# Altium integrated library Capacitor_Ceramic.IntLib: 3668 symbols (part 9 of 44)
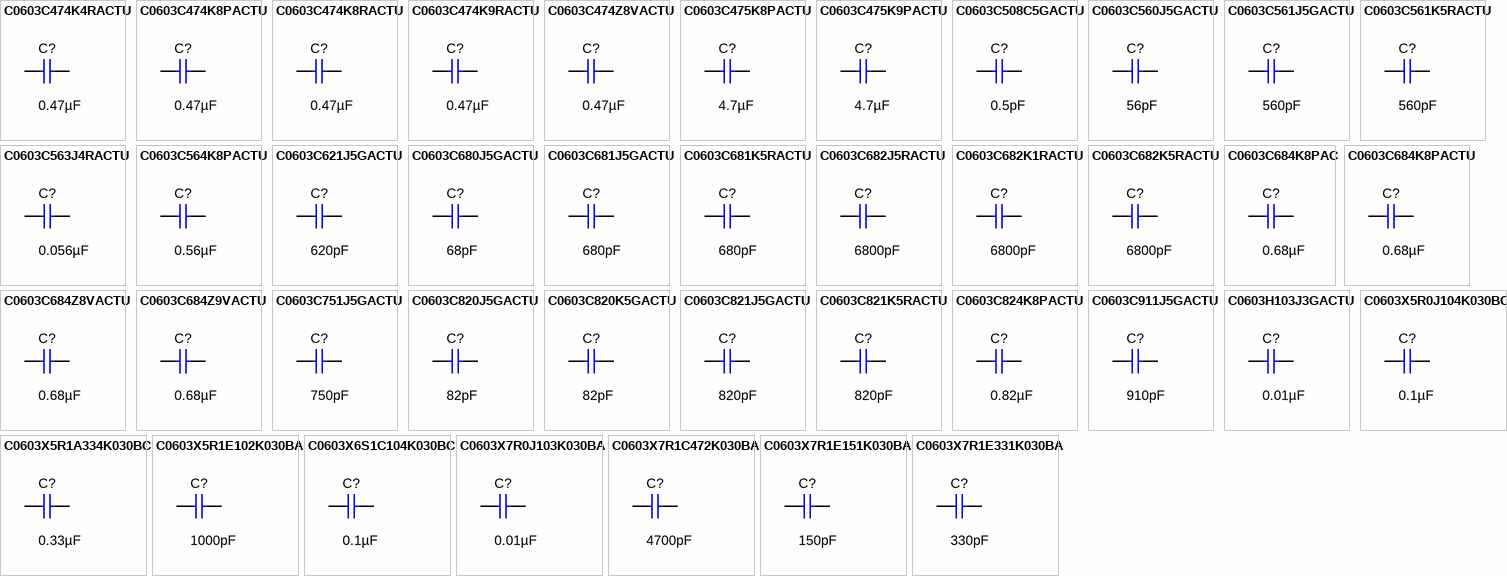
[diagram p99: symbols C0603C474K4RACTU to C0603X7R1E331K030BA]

## C0603C474Z8VACTU
designator C?  ValueDisplayed: 0.47µF  (hidden comment: C0603C474Z8VACTU)
CAP, CERM, 0.47 µF, 10 V,+80/-20%, Y5V, 0603; Manufacturer: Kemet; Polarized: N; CompType: Capacitor; Value: 0.47uF; U/M: EA; Cap_F: 0.00000047; Tolerance_%: 80; VDC_V: 10; Value2: 10V; TaMin_C: -30; TaMax_C: 85; Cap_Case: 0603; SizeArea_mm2: 1.28; SizeAreaWB_mm2: 4.68; SizeX_mm: 1.6; SizeY_mm: 0.8; SizeZ_mm: 1; AEC Category: Q200; Green_Lifecycle: Not Set; Green_REACh: Incomplete
signal-integrity model Cap
simulation model Cap
footprint 0603
footprint 0603M
footprint 0603L
footprint 0603_HV
footprint 0603S
pins: 1, 2

## C0603C475K8PACTU
designator C?  ValueDisplayed: 4.7µF  (hidden comment: C0603C475K8PACTU)
CAP, CERM, 4.7 µF, 10 V,+/- 10%, X5R, 0603; Manufacturer: Kemet; Polarized: N; CompType: Capacitor; Value: 4.7uF; U/M: EA; Cap_F: 0.0000047; Tolerance_%: 10; ESR_ohm: 0.006; Value1: 0.006 ohm; Value2: 10V; IRMS_A: 7.24; TaMin_C: -55; TaMax_C: 85; Cap_Case: 0603; SizeArea_mm2: 1.28; SizeAreaWB_mm2: 4.68; SizeX_mm: 1.6; SizeY_mm: 0.8; SizeZ_mm: 1; AEC Category: Q200; Green_Lifecycle: Active; Green_REACh: Passed
signal-integrity model Cap
simulation model Cap
footprint 0603
footprint 0603M
footprint 0603L
footprint 0603_HV
footprint 0603S
pins: 1, 2

## C0603C475K9PACTU
designator C?  ValueDisplayed: 4.7µF  (hidden comment: C0603C475K9PACTU)
CAP, CERM, 4.7 µF, 6.3 V,+/- 10%, X5R, 0603; Manufacturer: Kemet; Polarized: N; CompType: Capacitor; Value: 4.7uF; U/M: EA; Cap_F: 0.0000047; Tolerance_%: 10; ESR_ohm: 0.006; Value1: 0.006 ohm; VDC_V: 6.3; Value2: 6.3V; IRMS_A: 7.24; TaMin_C: -55; TaMax_C: 85; Cap_Case: 0603; SizeArea_mm2: 1.28; SizeAreaWB_mm2: 4.68; SizeX_mm: 1.6; SizeY_mm: 0.8; SizeZ_mm: 1; AEC Category: Q200; Green_Lifecycle: Active; Green_REACh: Passed
signal-integrity model Cap
simulation model Cap
footprint 0603
footprint 0603M
footprint 0603L
footprint 0603_HV
footprint 0603S
pins: 1, 2

## C0603C508C5GACTU
designator C?  ValueDisplayed: 0.5pF  (hidden comment: C0603C508C5GACTU)
CAP, CERM, 0.5 pF, 50 V,+/- 50%, C0G/NP0, 0603; Manufacturer: Kemet; Polarized: N; CompType: Capacitor; Value: 0.5pF; U/M: EA; Cap_F: 0.0000000000005; Tolerance_%: 50; Value2: 50V; TaMin_C: -55; TaMax_C: 125; Cap_Case: 0603; SizeArea_mm2: 1.28; SizeAreaWB_mm2: 4.68; SizeX_mm: 1.6; SizeY_mm: 0.8; SizeZ_mm: 1; AEC Category: Q200; Green_Lifecycle: Not Set; Green_REACh: Incomplete
signal-integrity model Cap
simulation model Cap
footprint 0603
footprint 0603M
footprint 0603L
footprint 0603_HV
footprint 0603S
pins: 1, 2

## C0603C560J5GACTU
designator C?  ValueDisplayed: 56pF  (hidden comment: C0603C560J5GACTU)
CAP, CERM, 56 pF, 50 V,+/- 5%, C0G/NP0, 0603; Manufacturer: Kemet; Polarized: N; CompType: Capacitor; Value: 56pF; U/M: EA; Cap_F: 0.000000000056; Tolerance_%: 5; VDC_V: 50; Value2: 50V; TaMin_C: -55; TaMax_C: 125; Cap_Case: 0603; SizeArea_mm2: 1.28; SizeAreaWB_mm2: 4.68; SizeX_mm: 1.6; SizeY_mm: 0.8; SizeZ_mm: 1; AEC Category: Q200; Green_Lifecycle: Active; Green_REACh: Passed
signal-integrity model Cap
simulation model Cap
footprint 0603
footprint 0603M
footprint 0603L
footprint 0603_HV
footprint 0603S
pins: 1, 2

## C0603C561J5GACTU
designator C?  ValueDisplayed: 560pF  (hidden comment: C0603C561J5GACTU)
CAP, CERM, 560 pF, 50 V,+/- 5%, C0G/NP0, 0603; Manufacturer: Kemet; Polarized: N; CompType: Capacitor; Value: 560pF; U/M: EA; Cap_F: 0.00000000056; Tolerance_%: 5; VDC_V: 50; Value2: 50V; TaMin_C: -55; TaMax_C: 125; Cap_Case: 0603; SizeArea_mm2: 1.28; SizeAreaWB_mm2: 4.68; SizeX_mm: 1.6; SizeY_mm: 0.8; SizeZ_mm: 1; AEC Category: Q200; Green_Lifecycle: Active; Green_REACh: Passed
signal-integrity model Cap
simulation model Cap
footprint 0603
footprint 0603M
footprint 0603L
footprint 0603_HV
footprint 0603S
pins: 1, 2

## C0603C561K5RACTU
designator C?  ValueDisplayed: 560pF  (hidden comment: C0603C561K5RACTU)
CAP, CERM, 560 pF, 50 V,+/- 10%, X7R, 0603; Manufacturer: Kemet; Polarized: N; CompType: Capacitor; Value: 560pF; U/M: EA; Cap_F: 0.00000000056; Tolerance_%: 10; VDC_V: 50; Value2: 50V; TaMin_C: -55; TaMax_C: 125; Cap_Case: 0603; SizeArea_mm2: 1.28; SizeAreaWB_mm2: 4.68; SizeX_mm: 1.6; SizeY_mm: 0.8; SizeZ_mm: 1; AEC Category: Q200; Green_Lifecycle: Not Set; Green_REACh: Incomplete
signal-integrity model Cap
simulation model Cap
footprint 0603
footprint 0603M
footprint 0603L
footprint 0603_HV
footprint 0603S
pins: 1, 2

## C0603C563J4RACTU
designator C?  ValueDisplayed: 0.056µF  (hidden comment: C0603C563J4RACTU)
CAP, CERM, 0.056 µF, 16 V,+/- 5%, X7R, 0603; Manufacturer: Kemet; Polarized: N; CompType: Capacitor; Value: 0.056uF; U/M: EA; Cap_F: 0.000000056; Tolerance_%: 5; VDC_V: 16; Value2: 16V; TaMin_C: -55; TaMax_C: 125; Cap_Case: 0603; SizeArea_mm2: 1.28; SizeAreaWB_mm2: 4.68; SizeX_mm: 1.6; SizeY_mm: 0.8; SizeZ_mm: 1; AEC Category: Q200
signal-integrity model Cap
simulation model Cap
footprint 0603
footprint 0603M
footprint 0603L
footprint 0603_HV
footprint 0603S
pins: 1, 2

## C0603C564K8PACTU
designator C?  ValueDisplayed: 0.56µF  (hidden comment: C0603C564K8PACTU)
CAP, CERM, 0.56 µF, 10 V,+/- 10%, X5R, 0603; Manufacturer: Kemet; Polarized: N; CompType: Capacitor; Value: 0.56uF; U/M: EA; Cap_F: 0.00000056; Tolerance_%: 10; Value2: 10V; TaMin_C: -55; TaMax_C: 85; Cap_Case: 0603; SizeArea_mm2: 1.28; SizeAreaWB_mm2: 4.68; SizeX_mm: 1.6; SizeY_mm: 0.8; SizeZ_mm: 1; AEC Category: Q200; Green_Lifecycle: Not Set; Green_REACh: Incomplete
signal-integrity model Cap
simulation model Cap
footprint 0603
footprint 0603M
footprint 0603L
footprint 0603_HV
footprint 0603S
pins: 1, 2

## C0603C621J5GACTU
designator C?  ValueDisplayed: 620pF  (hidden comment: C0603C621J5GACTU)
CAP, CERM, 620 pF, 50 V,+/- 5%, C0G/NP0, 0603; Manufacturer: Kemet; Polarized: N; CompType: Capacitor; Value: 620pF; U/M: EA; Cap_F: 0.00000000062; Tolerance_%: 5; VDC_V: 50; Value2: 50V; TaMin_C: -55; TaMax_C: 125; Cap_Case: 0603; SizeArea_mm2: 1.28; SizeAreaWB_mm2: 4.68; SizeX_mm: 1.6; SizeY_mm: 0.8; SizeZ_mm: 1; AEC Category: Q200; Green_Lifecycle: Not Set; Green_REACh: Incomplete
signal-integrity model Cap
simulation model Cap
footprint 0603
footprint 0603M
footprint 0603L
footprint 0603_HV
footprint 0603S
pins: 1, 2

## C0603C680J5GACTU
designator C?  ValueDisplayed: 68pF  (hidden comment: C0603C680J5GACTU)
CAP, CERM, 68 pF, 50 V,+/- 5%, C0G/NP0, 0603; Manufacturer: Kemet; Polarized: N; CompType: Capacitor; Value: 68pF; U/M: EA; Cap_F: 0.000000000068; Tolerance_%: 5; VDC_V: 50; Value2: 50V; TaMin_C: -55; TaMax_C: 125; Cap_Case: 0603; SizeArea_mm2: 1.28; SizeAreaWB_mm2: 4.68; SizeX_mm: 1.6; SizeY_mm: 0.8; SizeZ_mm: 1; AEC Category: Q200; Green_Lifecycle: Not Set; Green_REACh: Incomplete
signal-integrity model Cap
simulation model Cap
footprint 0603
footprint 0603M
footprint 0603L
footprint 0603_HV
footprint 0603S
pins: 1, 2

## C0603C681J5GACTU
designator C?  ValueDisplayed: 680pF  (hidden comment: C0603C681J5GACTU)
CAP, CERM, 680 pF, 50 V,+/- 5%, C0G/NP0, 0603; Manufacturer: Kemet; Polarized: N; CompType: Capacitor; Value: 680pF; U/M: EA; Cap_F: 0.00000000068; Tolerance_%: 5; VDC_V: 50; Value2: 50V; TaMin_C: -55; TaMax_C: 125; Cap_Case: 0603; SizeArea_mm2: 1.28; SizeAreaWB_mm2: 4.68; SizeX_mm: 1.6; SizeY_mm: 0.8; SizeZ_mm: 1; AEC Category: Q200; Green_Lifecycle: Not Set; Green_REACh: Incomplete
signal-integrity model Cap
simulation model Cap
footprint 0603
footprint 0603M
footprint 0603L
footprint 0603_HV
footprint 0603S
pins: 1, 2

## C0603C681K5RACTU
designator C?  ValueDisplayed: 680pF  (hidden comment: C0603C681K5RACTU)
CAP, CERM, 680 pF, 50 V,+/- 10%, X7R, 0603; Manufacturer: Kemet; Polarized: N; CompType: Capacitor; Value: 680pF; U/M: EA; Cap_F: 0.00000000068; Tolerance_%: 10; VDC_V: 50; Value2: 50V; TaMin_C: -55; TaMax_C: 125; Cap_Case: 0603; SizeArea_mm2: 1.28; SizeAreaWB_mm2: 4.68; SizeX_mm: 1.6; SizeY_mm: 0.8; SizeZ_mm: 1; AEC Category: Q200; Green_Lifecycle: Not Set; Green_REACh: Incomplete
signal-integrity model Cap
simulation model Cap
footprint 0603
footprint 0603M
footprint 0603L
footprint 0603_HV
footprint 0603S
pins: 1, 2

## C0603C682J5RACTU
designator C?  ValueDisplayed: 6800pF  (hidden comment: C0603C682J5RACTU)
CAP, CERM, 6800 pF, 50 V,+/- 5%, X7R, 0603; Manufacturer: Kemet; Polarized: N; CompType: Capacitor; Value: 6800pF; U/M: EA; Cap_F: 0.0000000068; Tolerance_%: 5; VDC_V: 50; Value2: 50V; TaMin_C: -55; TaMax_C: 125; Cap_Case: 0603; SizeArea_mm2: 1.28; SizeAreaWB_mm2: 4.68; SizeX_mm: 1.6; SizeY_mm: 0.8; SizeZ_mm: 1; AEC Category: Q200; Green_Lifecycle: Active; Green_REACh: Passed
signal-integrity model Cap
simulation model Cap
footprint 0603
footprint 0603M
footprint 0603L
footprint 0603_HV
footprint 0603S
pins: 1, 2

## C0603C682K1RACTU
designator C?  ValueDisplayed: 6800pF  (hidden comment: C0603C682K1RACTU)
CAP, CERM, 6800 pF, 100 V,+/- 10%, X7R, 0603; Manufacturer: Kemet; Polarized: N; CompType: Capacitor; Value: 6800pF; U/M: EA; Cap_F: 0.0000000068; Tolerance_%: 10; VDC_V: 100; Value2: 100V; TaMin_C: -55; TaMax_C: 125; Cap_Case: 0603; SizeArea_mm2: 1.28; SizeAreaWB_mm2: 4.68; SizeX_mm: 1.6; SizeY_mm: 0.8; SizeZ_mm: 1; AEC Category: Q200; Green_Lifecycle: Active; Green_REACh: Passed
signal-integrity model Cap
simulation model Cap
footprint 0603
footprint 0603M
footprint 0603L
footprint 0603_HV
footprint 0603S
pins: 1, 2

## C0603C682K5RACTU
designator C?  ValueDisplayed: 6800pF  (hidden comment: C0603C682K5RACTU)
CAP, CERM, 6800 pF, 50 V,+/- 10%, X7R, 0603; Manufacturer: Kemet; Polarized: N; CompType: Capacitor; Value: 6800pF; U/M: EA; Cap_F: 0.0000000068; Tolerance_%: 10; VDC_V: 50; Value2: 50V; TaMin_C: -55; TaMax_C: 125; Cap_Case: 0603; SizeArea_mm2: 1.28; SizeAreaWB_mm2: 4.68; SizeX_mm: 1.6; SizeY_mm: 0.8; SizeZ_mm: 1; AEC Category: Q200; Green_Lifecycle: Active; Green_REACh: Passed
signal-integrity model Cap
simulation model Cap
footprint 0603
footprint 0603M
footprint 0603L
footprint 0603_HV
footprint 0603S
pins: 1, 2

## C0603C684K8PAC
designator C?  ValueDisplayed: 0.68µF  (hidden comment: C0603C684K8PAC)
CAP, CERM, 0.68 µF, 10 V,+/- 10%, X5R, 0603; Manufacturer: Kemet; Polarized: N; CompType: Capacitor; Value: 0.68uF; U/M: EA; Cap_F: 0.00000068; Tolerance_%: 10; Value2: 10V; TaMin_C: -55; TaMax_C: 85; Cap_Case: 0603; SizeArea_mm2: 1.28; SizeAreaWB_mm2: 4.68; SizeX_mm: 1.6; SizeY_mm: 0.8; SizeZ_mm: 1; AEC Category: Q200; Green_Lifecycle: Not Set; Green_REACh: Incomplete
signal-integrity model Cap
simulation model Cap
footprint 0603
footprint 0603M
footprint 0603L
footprint 0603_HV
footprint 0603S
pins: 1, 2

## C0603C684K8PACTU
designator C?  ValueDisplayed: 0.68µF  (hidden comment: C0603C684K8PACTU)
CAP, CERM, 0.68 µF, 10 V,+/- 10%, X5R, 0603; Manufacturer: Kemet; Polarized: N; CompType: Capacitor; Value: 0.68uF; U/M: EA; Cap_F: 0.00000068; Tolerance_%: 10; Value2: 10V; TaMin_C: -55; TaMax_C: 85; Cap_Case: 0603; SizeArea_mm2: 1.28; SizeAreaWB_mm2: 4.68; SizeX_mm: 1.6; SizeY_mm: 0.8; SizeZ_mm: 1; AEC Category: Q200; Green_Lifecycle: Active; Green_REACh: Passed
signal-integrity model Cap
simulation model Cap
footprint 0603
footprint 0603M
footprint 0603L
footprint 0603_HV
footprint 0603S
pins: 1, 2

## C0603C684Z8VACTU
designator C?  ValueDisplayed: 0.68µF  (hidden comment: C0603C684Z8VACTU)
CAP, CERM, 0.68 µF, 10 V,+80/-20%, Y5V, 0603; Manufacturer: Kemet; Polarized: N; CompType: Capacitor; Value: 0.68uF; U/M: EA; Cap_F: 0.00000068; Tolerance_%: 80; VDC_V: 10; Value2: 10V; TaMin_C: -30; TaMax_C: 85; Cap_Case: 0603; SizeArea_mm2: 1.28; SizeAreaWB_mm2: 4.68; SizeX_mm: 1.6; SizeY_mm: 0.8; SizeZ_mm: 1; AEC Category: Q200; Green_Lifecycle: Not Set; Green_REACh: Incomplete
signal-integrity model Cap
simulation model Cap
footprint 0603
footprint 0603M
footprint 0603L
footprint 0603_HV
footprint 0603S
pins: 1, 2

## C0603C684Z9VACTU
designator C?  ValueDisplayed: 0.68µF  (hidden comment: C0603C684Z9VACTU)
CAP, CERM, 0.68 µF, 6.3 V,+80/-20%, Y5V, 0603; Manufacturer: Kemet; Polarized: N; CompType: Capacitor; Value: 0.68uF; U/M: EA; Cap_F: 0.00000068; Tolerance_%: 80; VDC_V: 6.3; Value2: 6.3V; TaMin_C: -30; TaMax_C: 85; Cap_Case: 0603; SizeArea_mm2: 1.28; SizeAreaWB_mm2: 4.68; SizeX_mm: 1.6; SizeY_mm: 0.8; SizeZ_mm: 1; AEC Category: Q200; Green_Lifecycle: Not Set; Green_REACh: Incomplete
signal-integrity model Cap
simulation model Cap
footprint 0603
footprint 0603M
footprint 0603L
footprint 0603_HV
footprint 0603S
pins: 1, 2

## C0603C751J5GACTU
designator C?  ValueDisplayed: 750pF  (hidden comment: C0603C751J5GACTU)
CAP, CERM, 750 pF, 50 V,+/- 5%, C0G/NP0, 0603; Manufacturer: Kemet; Polarized: N; CompType: Capacitor; Value: 750pF; U/M: EA; Cap_F: 0.00000000075; Tolerance_%: 5; VDC_V: 50; Value2: 50V; TaMin_C: -55; TaMax_C: 125; Cap_Case: 0603; SizeArea_mm2: 1.28; SizeAreaWB_mm2: 4.68; SizeX_mm: 1.6; SizeY_mm: 0.8; SizeZ_mm: 1; AEC Category: Q200; Green_Lifecycle: Active; Green_REACh: Passed
signal-integrity model Cap
simulation model Cap
footprint 0603
footprint 0603M
footprint 0603L
footprint 0603_HV
footprint 0603S
pins: 1, 2

## C0603C820J5GACTU
designator C?  ValueDisplayed: 82pF  (hidden comment: C0603C820J5GACTU)
CAP, CERM, 82 pF, 50 V,+/- 5%, C0G/NP0, 0603; Manufacturer: Kemet; Polarized: N; CompType: Capacitor; Value: 82pF; U/M: EA; Cap_F: 0.000000000082; Tolerance_%: 5; VDC_V: 50; Value2: 50V; TaMin_C: -55; TaMax_C: 125; Cap_Case: 0603; SizeArea_mm2: 1.28; SizeAreaWB_mm2: 4.68; SizeX_mm: 1.6; SizeY_mm: 0.8; SizeZ_mm: 1; AEC Category: Q200; Green_Lifecycle: Not Set; Green_REACh: Incomplete
signal-integrity model Cap
simulation model Cap
footprint 0603
footprint 0603M
footprint 0603L
footprint 0603_HV
footprint 0603S
pins: 1, 2

## C0603C820K5GACTU
designator C?  ValueDisplayed: 82pF  (hidden comment: C0603C820K5GACTU)
CAP, CERM, 82 pF, 50 V,+/- 10%, C0G/NP0, 0603; Manufacturer: Kemet; Polarized: N; CompType: Capacitor; Value: 82pF; U/M: EA; Cap_F: 0.000000000082; Tolerance_%: 10; VDC_V: 50; Value2: 50V; TaMin_C: -55; TaMax_C: 125; Cap_Case: 0603; SizeArea_mm2: 1.28; SizeAreaWB_mm2: 4.68; SizeX_mm: 1.6; SizeY_mm: 0.8; SizeZ_mm: 1; AEC Category: Q200; Green_Lifecycle: Active; Green_REACh: Passed
signal-integrity model Cap
simulation model Cap
footprint 0603
footprint 0603M
footprint 0603L
footprint 0603_HV
footprint 0603S
pins: 1, 2

## C0603C821J5GACTU
designator C?  ValueDisplayed: 820pF  (hidden comment: C0603C821J5GACTU)
CAP, CERM, 820 pF, 50 V,+/- 5%, C0G/NP0, 0603; Manufacturer: Kemet; Polarized: N; CompType: Capacitor; Value: 820pF; U/M: EA; Cap_F: 0.00000000082; Tolerance_%: 5; VDC_V: 50; Value2: 50V; TaMin_C: -55; TaMax_C: 125; Cap_Case: 0603; SizeArea_mm2: 1.28; SizeAreaWB_mm2: 4.68; SizeX_mm: 1.6; SizeY_mm: 0.8; SizeZ_mm: 1; AEC Category: Q200; Green_Lifecycle: Not Set; Green_REACh: Incomplete
signal-integrity model Cap
simulation model Cap
footprint 0603
footprint 0603M
footprint 0603L
footprint 0603_HV
footprint 0603S
pins: 1, 2

## C0603C821K5RACTU
designator C?  ValueDisplayed: 820pF  (hidden comment: C0603C821K5RACTU)
CAP, CERM, 820 pF, 50 V,+/- 10%, X7R, 0603; Manufacturer: Kemet; Polarized: N; CompType: Capacitor; Value: 820pF; U/M: EA; Cap_F: 0.00000000082; Tolerance_%: 10; VDC_V: 50; Value2: 50V; TaMin_C: -55; TaMax_C: 125; Cap_Case: 0603; SizeArea_mm2: 1.28; SizeAreaWB_mm2: 4.68; SizeX_mm: 1.6; SizeY_mm: 0.8; SizeZ_mm: 1; AEC Category: Q200; Green_Lifecycle: Active; Green_REACh: Passed
signal-integrity model Cap
simulation model Cap
footprint 0603
footprint 0603M
footprint 0603L
footprint 0603_HV
footprint 0603S
pins: 1, 2

## C0603C824K8PACTU
designator C?  ValueDisplayed: 0.82µF  (hidden comment: C0603C824K8PACTU)
CAP, CERM, 0.82 µF, 10 V,+/- 10%, X5R, 0603; Manufacturer: Kemet; Polarized: N; CompType: Capacitor; Value: 0.82uF; U/M: EA; Cap_F: 0.00000082; Tolerance_%: 10; Value2: 10V; TaMin_C: -55; TaMax_C: 85; Cap_Case: 0603; SizeArea_mm2: 1.28; SizeAreaWB_mm2: 4.68; SizeX_mm: 1.6; SizeY_mm: 0.8; SizeZ_mm: 1; AEC Category: Q200; Green_Lifecycle: Not Set; Green_REACh: Incomplete
signal-integrity model Cap
simulation model Cap
footprint 0603
footprint 0603M
footprint 0603L
footprint 0603_HV
footprint 0603S
pins: 1, 2

## C0603C911J5GACTU
designator C?  ValueDisplayed: 910pF  (hidden comment: C0603C911J5GACTU)
CAP, CERM, 910 pF, 50 V,+/- 5%, C0G/NP0, 0603; Manufacturer: Kemet; Polarized: N; CompType: Capacitor; Value: 910pF; U/M: EA; Cap_F: 0.00000000091; Tolerance_%: 5; VDC_V: 50; Value2: 50V; TaMin_C: -55; TaMax_C: 125; Cap_Case: 0603; SizeArea_mm2: 1.28; SizeAreaWB_mm2: 4.68; SizeX_mm: 1.6; SizeY_mm: 0.8; SizeZ_mm: 1; AEC Category: Q200; Green_Lifecycle: Not Set; Green_REACh: Incomplete
signal-integrity model Cap
simulation model Cap
footprint 0603
footprint 0603M
footprint 0603L
footprint 0603_HV
footprint 0603S
pins: 1, 2

## C0603H103J3GACTU
designator C?  ValueDisplayed: 0.01µF  (hidden comment: C0603H103J3GACTU)
CAP, CERM, 0.01 µF, 25 V,+/- 5%, C0G/NP0, 0603; Manufacturer: Kemet; Polarized: N; CompType: Capacitor; Value: 0.01uF; U/M: EA; Cap_F: 0.00000001; Tolerance_%: 5; VDC_V: 25; Value2: 25V; TaMin_C: -55; TaMax_C: 200; Cap_Case: 0603; SizeArea_mm2: 1.28; SizeAreaWB_mm2: 4.68; SizeX_mm: 1.6; SizeY_mm: 0.8; SizeZ_mm: 1; AEC Category: Q200; Green_Lifecycle: Active; Green_REACh: Passed
signal-integrity model Cap
simulation model Cap
footprint 0603
footprint 0603M
footprint 0603L
footprint 0603_HV
footprint 0603S
pins: 1, 2

## C0603X5R0J104K030BC
designator C?  ValueDisplayed: 0.1µF  (hidden comment: C0603X5R0J104K030BC)
CAP, CERM, 0.1 µF, 6.3 V,+/- 10%, X5R, 0201; Manufacturer: TDK; Polarized: N; CompType: Capacitor; Value: 0.1uF; U/M: EA; Cap_F: 0.0000001; Tolerance_%: 10; VDC_V: 6.3; Value2: 6.3V; TaMin_C: -55; TaMax_C: 85; Cap_Case: 0201; SizeArea_mm2: 0.18; SizeAreaWB_mm2: 2.08; SizeX_mm: 0.6; SizeY_mm: 0.3; SizeZ_mm: 0.26; AEC Category: Q200; Green_Lifecycle: EOL; Green_REACh: Passed
signal-integrity model Cap
simulation model Cap
footprint 0201
footprint 0201M
footprint 0201L
footprint 0201_Silk
pins: 1, 2

## C0603X5R1A334K030BC
designator C?  ValueDisplayed: 0.33µF  (hidden comment: C0603X5R1A334K030BC)
CAP, CERM, 0.33 µF, 10 V,+/- 10%, X5R, 0201; Manufacturer: TDK; Polarized: N; CompType: Capacitor; Value: 0.33uF; U/M: EA; Cap_F: 0.00000033; Tolerance_%: 10; Value2: 10V; TaMin_C: -55; TaMax_C: 85; Cap_Case: 0201; SizeArea_mm2: 0.18; SizeAreaWB_mm2: 2.08; SizeX_mm: 0.6; SizeY_mm: 0.3; SizeZ_mm: 0.33; AEC Category: Q200
signal-integrity model Cap
simulation model Cap
footprint 0201_033
footprint 0201_033M
footprint 0201_033L
pins: 1, 2

## C0603X5R1E102K030BA
designator C?  ValueDisplayed: 1000pF  (hidden comment: C0603X5R1E102K030BA)
CAP, CERM, 1000 pF, 25 V,+/- 10%, X5R, 0201; Manufacturer: TDK; Polarized: N; CompType: Capacitor; Value: 1000pF; U/M: EA; Cap_F: 0.000000001; Tolerance_%: 10; VDC_V: 25; Value2: 25V; TaMin_C: -55; TaMax_C: 85; Cap_Case: 0201; SizeArea_mm2: 0.18; SizeAreaWB_mm2: 2.08; SizeX_mm: 0.6; SizeY_mm: 0.3; SizeZ_mm: 0.33; AEC Category: Q200; Green_Lifecycle: Not Set; Green_REACh: Incomplete
signal-integrity model Cap
simulation model Cap
footprint 0201_033
footprint 0201_033M
footprint 0201_033L
pins: 1, 2

## C0603X6S1C104K030BC
designator C?  ValueDisplayed: 0.1µF  (hidden comment: C0603X6S1C104K030BC)
CAP, CERM, 0.1 µF, 16 V,+/- 10%, X6S, 0201; Manufacturer: TDK; Polarized: N; CompType: Capacitor; Value: 0.1uF; U/M: EA; Cap_F: 0.0000001; Tolerance_%: 10; VDC_V: 16; Value2: 16V; TaMin_C: -55; TaMax_C: 105; Cap_Case: 0201; SizeArea_mm2: 0.18; SizeAreaWB_mm2: 2.08; SizeX_mm: 0.6; SizeY_mm: 0.3; SizeZ_mm: 0.33; AEC Category: Q200
signal-integrity model Cap
simulation model Cap
footprint 0201_033
footprint 0201_033M
footprint 0201_033L
pins: 1, 2

## C0603X7R0J103K030BA
designator C?  ValueDisplayed: 0.01µF  (hidden comment: C0603X7R0J103K030BA)
CAP, CERM, 0.01 µF, 6.3 V,+/- 10%, X7R, 0201; Manufacturer: TDK; Polarized: N; CompType: Capacitor; Value: 0.01uF; U/M: EA; Cap_F: 0.00000001; Tolerance_%: 10; VDC_V: 6.3; Value2: 6.3V; TaMin_C: -55; TaMax_C: 125; Cap_Case: 0201; SizeArea_mm2: 0.18; SizeAreaWB_mm2: 2.08; SizeX_mm: 0.6; SizeY_mm: 0.3; SizeZ_mm: 0.33; AEC Category: Q200
signal-integrity model Cap
simulation model Cap
footprint 0201_033
footprint 0201_033M
footprint 0201_033L
pins: 1, 2

## C0603X7R1C472K030BA
designator C?  ValueDisplayed: 4700pF  (hidden comment: C0603X7R1C472K030BA)
CAP, CERM, 4700 pF, 16 V,+/- 10%, X7R, 0201; Manufacturer: TDK; Polarized: N; CompType: Capacitor; Value: 4700pF; U/M: EA; Cap_F: 0.0000000047; Tolerance_%: 10; VDC_V: 16; Value2: 16V; TaMin_C: -55; TaMax_C: 125; Cap_Case: 0201; SizeArea_mm2: 0.18; SizeAreaWB_mm2: 2.08; SizeX_mm: 0.6; SizeY_mm: 0.3; SizeZ_mm: 0.33; AEC Category: Q200
signal-integrity model Cap
simulation model Cap
footprint 0201_033
footprint 0201_033M
footprint 0201_033L
pins: 1, 2

## C0603X7R1E151K030BA
designator C?  ValueDisplayed: 150pF  (hidden comment: C0603X7R1E151K030BA)
CAP, CERM, 150 pF, 25 V,+/- 10%, X7R, 0201; Manufacturer: TDK; Polarized: N; CompType: Capacitor; Value: 150pF; U/M: EA; Cap_F: 0.00000000015; Tolerance_%: 10; VDC_V: 25; Value2: 25V; TaMin_C: -55; TaMax_C: 125; Cap_Case: 0201; SizeArea_mm2: 0.18; SizeAreaWB_mm2: 2.08; SizeX_mm: 0.6; SizeY_mm: 0.3; SizeZ_mm: 0.33; AEC Category: Q200; Green_Lifecycle: Not Set; Green_REACh: Incomplete
signal-integrity model Cap
simulation model Cap
footprint 0201_033
footprint 0201_033M
footprint 0201_033L
pins: 1, 2

## C0603X7R1E331K030BA
designator C?  ValueDisplayed: 330pF  (hidden comment: C0603X7R1E331K030BA)
CAP, CERM, 330 pF, 25 V,+/- 10%, X7R, 0201; Manufacturer: TDK; Polarized: N; CompType: Capacitor; Value: 330pF; U/M: EA; Cap_F: 0.00000000033; Tolerance_%: 10; VDC_V: 25; Value2: 25V; TaMin_C: -55; TaMax_C: 125; Cap_Case: 0201; SizeArea_mm2: 0.18; SizeAreaWB_mm2: 2.08; SizeX_mm: 0.6; SizeY_mm: 0.3; SizeZ_mm: 0.33; AEC Category: Q200; Green_Lifecycle: Not Set; Green_REACh: Incomplete
signal-integrity model Cap
simulation model Cap
footprint 0201_033
footprint 0201_033M
footprint 0201_033L
pins: 1, 2

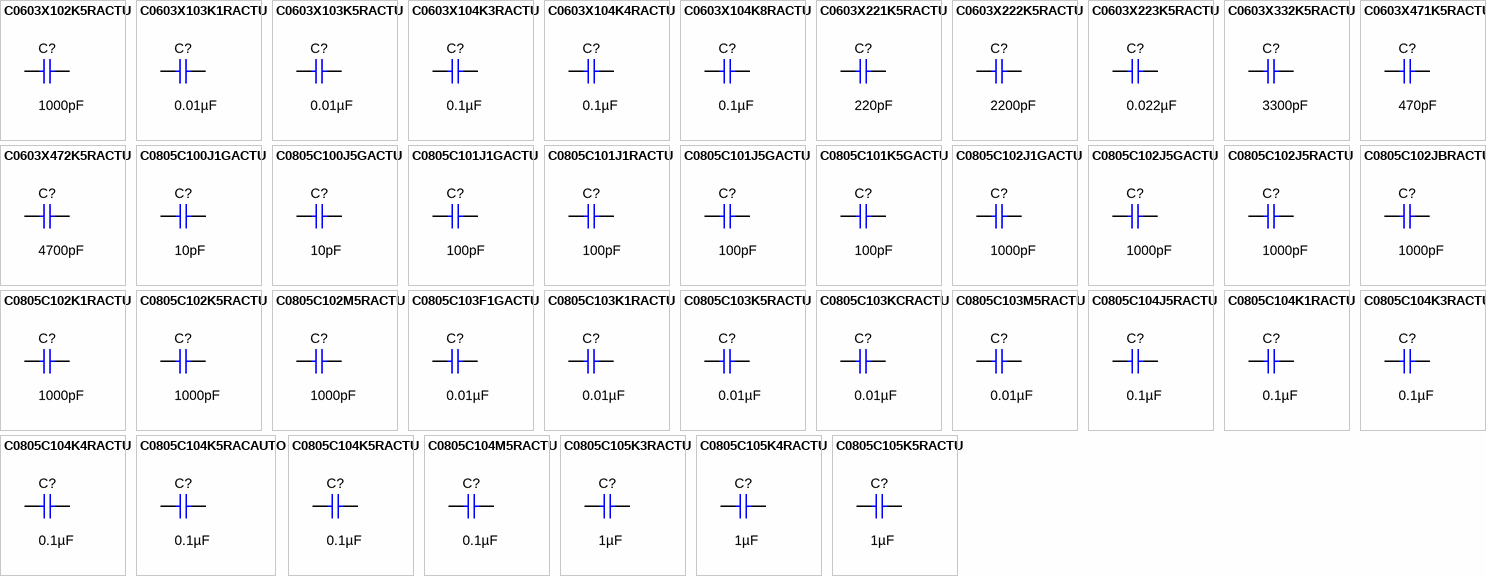
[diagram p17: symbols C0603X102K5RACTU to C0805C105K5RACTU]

## C0603X102K5RACTU
designator C?  ValueDisplayed: 1000pF  (hidden comment: C0603X102K5RACTU)
CAP, CERM, 1000 pF, 50 V,+/- 10%, X7R, 0603; Manufacturer: Kemet; Polarized: N; CompType: Capacitor; Value: 1000pF; U/M: EA; Cap_F: 0.000000001; Tolerance_%: 10; VDC_V: 50; Value2: 50V; TaMin_C: -55; TaMax_C: 125; Cap_Case: 0603; SizeArea_mm2: 1.28; SizeAreaWB_mm2: 4.68; SizeX_mm: 1.6; SizeY_mm: 0.8; SizeZ_mm: 1; AEC Category: Q200; Green_Lifecycle: Active; Green_REACh: Passed
signal-integrity model Cap
simulation model Cap
footprint 0603
footprint 0603M
footprint 0603L
footprint 0603_HV
footprint 0603S
pins: 1, 2

## C0603X103K1RACTU
designator C?  ValueDisplayed: 0.01µF  (hidden comment: C0603X103K1RACTU)
CAP, CERM, 0.01 µF, 100 V,+/- 10%, X7R, 0603; Manufacturer: Kemet; Polarized: N; CompType: Capacitor; Value: 0.01uF; U/M: EA; Cap_F: 0.00000001; Tolerance_%: 10; VDC_V: 100; Value2: 100V; TaMin_C: -55; TaMax_C: 125; Cap_Case: 0603; SizeArea_mm2: 1.28; SizeAreaWB_mm2: 4.68; SizeX_mm: 1.6; SizeY_mm: 0.8; SizeZ_mm: 1; AEC Category: Q200; Green_Lifecycle: Not Set; Green_REACh: Incomplete
signal-integrity model Cap
simulation model Cap
footprint 0603
footprint 0603M
footprint 0603L
footprint 0603_HV
footprint 0603S
pins: 1, 2

## C0603X103K5RACTU
designator C?  ValueDisplayed: 0.01µF  (hidden comment: C0603X103K5RACTU)
CAP, CERM, 0.01 µF, 50 V,+/- 10%, X7R, 0603; Manufacturer: Kemet; Polarized: N; CompType: Capacitor; Value: 0.01uF; U/M: EA; Cap_F: 0.00000001; Tolerance_%: 10; VDC_V: 50; Value2: 50V; TaMin_C: -55; TaMax_C: 125; Cap_Case: 0603; SizeArea_mm2: 1.28; SizeAreaWB_mm2: 4.68; SizeX_mm: 1.6; SizeY_mm: 0.8; SizeZ_mm: 1; AEC Category: Q200; Green_Lifecycle: Active; Green_REACh: Passed
signal-integrity model Cap
simulation model Cap
footprint 0603
footprint 0603M
footprint 0603L
footprint 0603_HV
footprint 0603S
pins: 1, 2

## C0603X104K3RACTU
designator C?  ValueDisplayed: 0.1µF  (hidden comment: C0603X104K3RACTU)
CAP, CERM, 0.1 µF, 25 V,+/- 10%, X7R, 0603; Manufacturer: Kemet; Polarized: N; CompType: Capacitor; Value: 0.1uF; U/M: EA; Cap_F: 0.0000001; Tolerance_%: 10; VDC_V: 25; Value2: 25V; TaMin_C: -55; TaMax_C: 125; Cap_Case: 0603; SizeArea_mm2: 1.28; SizeAreaWB_mm2: 4.68; SizeX_mm: 1.6; SizeY_mm: 0.8; SizeZ_mm: 1; AEC Category: Q200; Green_Lifecycle: Active; Green_REACh: Passed
signal-integrity model Cap
simulation model Cap
footprint 0603
footprint 0603M
footprint 0603L
footprint 0603_HV
footprint 0603S
pins: 1, 2

## C0603X104K4RACTU
designator C?  ValueDisplayed: 0.1µF  (hidden comment: C0603X104K4RACTU)
CAP, CERM, 0.1 µF, 16 V,+/- 10%, X7R, 0603; Manufacturer: Kemet; Polarized: N; CompType: Capacitor; Value: 0.1uF; U/M: EA; Cap_F: 0.0000001; Tolerance_%: 10; VDC_V: 16; Value2: 16V; TaMin_C: -55; TaMax_C: 125; Cap_Case: 0603; SizeArea_mm2: 1.28; SizeAreaWB_mm2: 4.68; SizeX_mm: 1.6; SizeY_mm: 0.8; SizeZ_mm: 1; AEC Category: Q200; Green_Lifecycle: Active; Green_REACh: Passed
signal-integrity model Cap
simulation model Cap
footprint 0603
footprint 0603M
footprint 0603L
footprint 0603_HV
footprint 0603S
pins: 1, 2

## C0603X104K8RACTU
designator C?  ValueDisplayed: 0.1µF  (hidden comment: C0603X104K8RACTU)
CAP, CERM, 0.1 µF, 10 V,+/- 10%, X7R, 0603; Manufacturer: Kemet; Polarized: N; CompType: Capacitor; Value: 0.1uF; U/M: EA; Cap_F: 0.0000001; Tolerance_%: 10; Value2: 10V; TaMin_C: -55; TaMax_C: 125; Cap_Case: 0603; SizeArea_mm2: 1.28; SizeAreaWB_mm2: 4.68; SizeX_mm: 1.6; SizeY_mm: 0.8; SizeZ_mm: 1; AEC Category: Q200; Green_Lifecycle: Not Set; Green_REACh: Incomplete
signal-integrity model Cap
simulation model Cap
footprint 0603
footprint 0603M
footprint 0603L
footprint 0603_HV
footprint 0603S
pins: 1, 2

## C0603X221K5RACTU
designator C?  ValueDisplayed: 220pF  (hidden comment: C0603X221K5RACTU)
CAP, CERM, 220 pF, 50 V,+/- 10%, X7R, 0603; Manufacturer: Kemet; Polarized: N; CompType: Capacitor; Value: 220pF; U/M: EA; Cap_F: 0.00000000022; Tolerance_%: 10; VDC_V: 50; Value2: 50V; TaMin_C: -55; TaMax_C: 125; Cap_Case: 0603; SizeArea_mm2: 1.28; SizeAreaWB_mm2: 4.68; SizeX_mm: 1.6; SizeY_mm: 0.8; SizeZ_mm: 1; AEC Category: Q200; Green_Lifecycle: Not Set; Green_REACh: Incomplete
signal-integrity model Cap
simulation model Cap
footprint 0603
footprint 0603M
footprint 0603L
footprint 0603_HV
footprint 0603S
pins: 1, 2

## C0603X222K5RACTU
designator C?  ValueDisplayed: 2200pF  (hidden comment: C0603X222K5RACTU)
CAP, CERM, 2200 pF, 50 V,+/- 10%, X7R, 0603; Manufacturer: Kemet; Polarized: N; CompType: Capacitor; Value: 2200pF; U/M: EA; Cap_F: 0.0000000022; Tolerance_%: 10; VDC_V: 50; Value2: 50V; TaMin_C: -55; TaMax_C: 125; Cap_Case: 0603; SizeArea_mm2: 1.28; SizeAreaWB_mm2: 4.68; SizeX_mm: 1.6; SizeY_mm: 0.8; SizeZ_mm: 1; AEC Category: Q200; Green_Lifecycle: Active; Green_REACh: Passed
signal-integrity model Cap
simulation model Cap
footprint 0603
footprint 0603M
footprint 0603L
footprint 0603_HV
footprint 0603S
pins: 1, 2

## C0603X223K5RACTU
designator C?  ValueDisplayed: 0.022µF  (hidden comment: C0603X223K5RACTU)
CAP, CERM, 0.022 µF, 50 V,+/- 10%, X7R, 0603; Manufacturer: Kemet; Polarized: N; CompType: Capacitor; Value: 0.022uF; U/M: EA; Cap_F: 0.000000022; Tolerance_%: 10; VDC_V: 50; Value2: 50V; TaMin_C: -55; TaMax_C: 125; Cap_Case: 0603; SizeArea_mm2: 1.28; SizeAreaWB_mm2: 4.68; SizeX_mm: 1.6; SizeY_mm: 0.8; SizeZ_mm: 1; AEC Category: Q200; Green_Lifecycle: Active; Green_REACh: Passed
signal-integrity model Cap
simulation model Cap
footprint 0603
footprint 0603M
footprint 0603L
footprint 0603_HV
footprint 0603S
pins: 1, 2

## C0603X332K5RACTU
designator C?  ValueDisplayed: 3300pF  (hidden comment: C0603X332K5RACTU)
CAP, CERM, 3300 pF, 50 V,+/- 10%, X7R, 0603; Manufacturer: Kemet; Polarized: N; CompType: Capacitor; Value: 3300pF; U/M: EA; Cap_F: 0.0000000033; Tolerance_%: 10; VDC_V: 50; Value2: 50V; TaMin_C: -55; TaMax_C: 125; Cap_Case: 0603; SizeArea_mm2: 1.28; SizeAreaWB_mm2: 4.68; SizeX_mm: 1.6; SizeY_mm: 0.8; SizeZ_mm: 1; AEC Category: Q200; Green_Lifecycle: Not Set; Green_REACh: Incomplete
signal-integrity model Cap
simulation model Cap
footprint 0603
footprint 0603M
footprint 0603L
footprint 0603_HV
footprint 0603S
pins: 1, 2

## C0603X471K5RACTU
designator C?  ValueDisplayed: 470pF  (hidden comment: C0603X471K5RACTU)
CAP, CERM, 470 pF, 50 V,+/- 10%, X7R, 0603; Manufacturer: Kemet; Polarized: N; CompType: Capacitor; Value: 470pF; U/M: EA; Cap_F: 0.00000000047; Tolerance_%: 10; VDC_V: 50; Value2: 50V; TaMin_C: -55; TaMax_C: 125; Cap_Case: 0603; SizeArea_mm2: 1.28; SizeAreaWB_mm2: 4.68; SizeX_mm: 1.6; SizeY_mm: 0.8; SizeZ_mm: 1; AEC Category: Q200; Green_Lifecycle: Not Set; Green_REACh: Incomplete
signal-integrity model Cap
simulation model Cap
footprint 0603
footprint 0603M
footprint 0603L
footprint 0603_HV
footprint 0603S
pins: 1, 2

## C0603X472K5RACTU
designator C?  ValueDisplayed: 4700pF  (hidden comment: C0603X472K5RACTU)
CAP, CERM, 4700 pF, 50 V,+/- 10%, X7R, 0603; Manufacturer: Kemet; Polarized: N; CompType: Capacitor; Value: 4700pF; U/M: EA; Cap_F: 0.0000000047; Tolerance_%: 10; VDC_V: 50; Value2: 50V; TaMin_C: -55; TaMax_C: 125; Cap_Case: 0603; SizeArea_mm2: 1.28; SizeAreaWB_mm2: 4.68; SizeX_mm: 1.6; SizeY_mm: 0.8; SizeZ_mm: 1; AEC Category: Q200; Green_Lifecycle: Active; Green_REACh: Passed
signal-integrity model Cap
simulation model Cap
footprint 0603
footprint 0603M
footprint 0603L
footprint 0603_HV
footprint 0603S
pins: 1, 2

## C0805C100J1GACTU
designator C?  ValueDisplayed: 10pF  (hidden comment: C0805C100J1GACTU)
CAP, CERM, 10 pF, 100 V,+/- 5%, C0G/NP0, 0805; Manufacturer: Kemet; Polarized: N; CompType: Capacitor; Value: 10pF; U/M: EA; Cap_F: 0.00000000001; Tolerance_%: 5; ESR_ohm: 0.285; Value1: 0.285 ohm; VDC_V: 100; Value2: 100V; IRMS_A: 0.221; TaMin_C: -55; TaMax_C: 125; Cap_Case: 0805; SizeArea_mm2: 2.5; SizeAreaWB_mm2: 6.75; SizeX_mm: 2; SizeY_mm: 1.25; SizeZ_mm: 1.45; AEC Category: Q200; Green_Lifecycle: Not Set; Green_REACh: Incomplete
signal-integrity model Cap
simulation model Cap
footprint 0805_HV
footprint 0805_HV1
footprint 0805
footprint 0805M
footprint 0805L
pins: 1, 2

## C0805C100J5GACTU
designator C?  ValueDisplayed: 10pF  (hidden comment: C0805C100J5GACTU)
CAP, CERM, 10 pF, 50 V,+/- 5%, C0G/NP0, 0805; Manufacturer: Kemet; Polarized: N; CompType: Capacitor; Value: 10pF; U/M: EA; Cap_F: 0.00000000001; Tolerance_%: 5; ESR_ohm: 0.285; Value1: 0.285 ohm; VDC_V: 50; Value2: 50V; IRMS_A: 0.221; TaMin_C: -55; TaMax_C: 125; Cap_Case: 0805; SizeArea_mm2: 2.5; SizeAreaWB_mm2: 6.75; SizeX_mm: 2; SizeY_mm: 1.25; SizeZ_mm: 1.45; AEC Category: Q200; Green_Lifecycle: Not Set; Green_REACh: Incomplete
signal-integrity model Cap
simulation model Cap
footprint 0805_HV
footprint 0805_HV1
footprint 0805
footprint 0805M
footprint 0805L
pins: 1, 2

## C0805C101J1GACTU
designator C?  ValueDisplayed: 100pF  (hidden comment: C0805C101J1GACTU)
CAP, CERM, 100 pF, 100 V,+/- 5%, C0G/NP0, 0805; Manufacturer: Kemet; Polarized: N; CompType: Capacitor; Value: 100pF; U/M: EA; Cap_F: 0.0000000001; Tolerance_%: 5; ESR_ohm: 0.074; Value1: 0.074 ohm; VDC_V: 100; Value2: 100V; IRMS_A: 0.524; TaMin_C: -55; TaMax_C: 125; Cap_Case: 0805; SizeArea_mm2: 2.5; SizeAreaWB_mm2: 6.75; SizeX_mm: 2; SizeY_mm: 1.25; SizeZ_mm: 1.45; AEC Category: Q200; Green_Lifecycle: Active; Green_REACh: Passed
signal-integrity model Cap
simulation model Cap
footprint 0805_HV
footprint 0805_HV1
footprint 0805
footprint 0805M
footprint 0805L
pins: 1, 2

## C0805C101J1RACTU
designator C?  ValueDisplayed: 100pF  (hidden comment: C0805C101J1RACTU)
CAP, CERM, 100 pF, 100 V,+/- 5%, X7R, 0805; Manufacturer: Kemet; Polarized: N; CompType: Capacitor; Value: 100pF; U/M: EA; Cap_F: 0.0000000001; Tolerance_%: 5; VDC_V: 100; Value2: 100V; TaMin_C: -55; TaMax_C: 125; Cap_Case: 0805; SizeArea_mm2: 2.5; SizeAreaWB_mm2: 6.75; SizeX_mm: 2; SizeY_mm: 1.25; SizeZ_mm: 1.45; AEC Category: Q200; Green_Lifecycle: Not Set; Green_REACh: Incomplete
signal-integrity model Cap
simulation model Cap
footprint 0805_HV
footprint 0805_HV1
footprint 0805
footprint 0805M
footprint 0805L
pins: 1, 2

## C0805C101J5GACTU
designator C?  ValueDisplayed: 100pF  (hidden comment: C0805C101J5GACTU)
CAP, CERM, 100 pF, 50 V,+/- 5%, C0G/NP0, 0805; Manufacturer: Kemet; Polarized: N; CompType: Capacitor; Value: 100pF; U/M: EA; Cap_F: 0.0000000001; Tolerance_%: 5; ESR_ohm: 0.074; Value1: 0.074 ohm; VDC_V: 50; Value2: 50V; IRMS_A: 0.524; TaMin_C: -55; TaMax_C: 125; Cap_Case: 0805; SizeArea_mm2: 2.5; SizeAreaWB_mm2: 6.75; SizeX_mm: 2; SizeY_mm: 1.25; SizeZ_mm: 1.45; AEC Category: Q200; Green_Lifecycle: Active; Green_REACh: Passed
signal-integrity model Cap
simulation model Cap
footprint 0805_HV
footprint 0805_HV1
footprint 0805
footprint 0805M
footprint 0805L
pins: 1, 2

## C0805C101K5GACTU
designator C?  ValueDisplayed: 100pF  (hidden comment: C0805C101K5GACTU)
CAP, CERM, 100 pF, 50 V,+/- 10%, C0G/NP0, 0805; Manufacturer: Kemet; Polarized: N; CompType: Capacitor; Value: 100pF; U/M: EA; Cap_F: 0.0000000001; Tolerance_%: 10; ESR_ohm: 0.074; Value1: 0.074 ohm; VDC_V: 50; Value2: 50V; IRMS_A: 0.524; TaMin_C: -55; TaMax_C: 125; Cap_Case: 0805; SizeArea_mm2: 2.5; SizeAreaWB_mm2: 6.75; SizeX_mm: 2; SizeY_mm: 1.25; SizeZ_mm: 1.45; AEC Category: Q200; Green_Lifecycle: Active; Green_REACh: Passed
signal-integrity model Cap
simulation model Cap
footprint 0805_HV
footprint 0805_HV1
footprint 0805
footprint 0805M
footprint 0805L
pins: 1, 2

## C0805C102J1GACTU
designator C?  ValueDisplayed: 1000pF  (hidden comment: C0805C102J1GACTU)
CAP, CERM, 1000 pF, 100 V,+/- 5%, C0G/NP0, 0805; Manufacturer: Kemet; Polarized: N; CompType: Capacitor; Value: 1000pF; U/M: EA; Cap_F: 0.000000001; Tolerance_%: 5; ESR_ohm: 0.025; Value1: 0.025 ohm; VDC_V: 100; Value2: 100V; IRMS_A: 1.71; TaMin_C: -55; TaMax_C: 125; Cap_Case: 0805; SizeArea_mm2: 2.5; SizeAreaWB_mm2: 6.75; SizeX_mm: 2; SizeY_mm: 1.25; SizeZ_mm: 1.45; AEC Category: Q200; Green_Lifecycle: Not Set; Green_REACh: Incomplete
signal-integrity model Cap
simulation model Cap
footprint 0805_HV
footprint 0805_HV1
footprint 0805
footprint 0805M
footprint 0805L
pins: 1, 2

## C0805C102J5GACTU
designator C?  ValueDisplayed: 1000pF  (hidden comment: C0805C102J5GACTU)
CAP, CERM, 1000 pF, 50 V,+/- 5%, C0G/NP0, 0805; Manufacturer: Kemet; Polarized: N; CompType: Capacitor; Value: 1000pF; U/M: EA; Cap_F: 0.000000001; Tolerance_%: 5; ESR_ohm: 0.025; Value1: 0.025 ohm; VDC_V: 50; Value2: 50V; IRMS_A: 1.71; TaMin_C: -55; TaMax_C: 125; Cap_Case: 0805; SizeArea_mm2: 2.5; SizeAreaWB_mm2: 6.75; SizeX_mm: 2; SizeY_mm: 1.25; SizeZ_mm: 1.45; AEC Category: Q200; Green_Lifecycle: Active; Green_REACh: Passed
signal-integrity model Cap
simulation model Cap
footprint 0805_HV
footprint 0805_HV1
footprint 0805
footprint 0805M
footprint 0805L
pins: 1, 2

## C0805C102J5RACTU
designator C?  ValueDisplayed: 1000pF  (hidden comment: C0805C102J5RACTU)
CAP, CERM, 1000 pF, 50 V,+/- 5%, X7R, 0805; Manufacturer: Kemet; Polarized: N; CompType: Capacitor; Value: 1000pF; U/M: EA; Cap_F: 0.000000001; Tolerance_%: 5; ESR_ohm: 0.384; Value1: 0.384 ohm; VDC_V: 50; Value2: 50V; IRMS_A: 0.214; TaMin_C: -55; TaMax_C: 125; Cap_Case: 0805; SizeArea_mm2: 2.5; SizeAreaWB_mm2: 6.75; SizeX_mm: 2; SizeY_mm: 1.25; SizeZ_mm: 1.45; AEC Category: Q200; Green_Lifecycle: Not Set; Green_REACh: Incomplete
signal-integrity model Cap
simulation model Cap
footprint 0805_HV
footprint 0805_HV1
footprint 0805
footprint 0805M
footprint 0805L
pins: 1, 2

## C0805C102JBRACTU
designator C?  ValueDisplayed: 1000pF  (hidden comment: C0805C102JBRACTU)
CAP, CERM, 1000 pF, 630 V,+/- 5%, X7R, 0805; Manufacturer: Kemet; Polarized: N; CompType: Capacitor; Value: 1000pF; U/M: EA; Cap_F: 0.000000001; Tolerance_%: 5; VDC_V: 630; Value2: 630V; TaMin_C: -55; TaMax_C: 125; Cap_Case: 0805; SizeArea_mm2: 2.5; SizeAreaWB_mm2: 6.75; SizeX_mm: 2; SizeY_mm: 1.25; SizeZ_mm: 1.45; AEC Category: Q200
signal-integrity model Cap
simulation model Cap
footprint 0805_HV
footprint 0805_HV1
footprint 0805
footprint 0805M
footprint 0805L
pins: 1, 2

## C0805C102K1RACTU
designator C?  ValueDisplayed: 1000pF  (hidden comment: C0805C102K1RACTU)
CAP, CERM, 1000 pF, 100 V,+/- 10%, X7R, 0805; Manufacturer: Kemet; Polarized: N; CompType: Capacitor; Value: 1000pF; U/M: EA; Cap_F: 0.000000001; Tolerance_%: 10; ESR_ohm: 0.384; Value1: 0.384 ohm; VDC_V: 100; Value2: 100V; IRMS_A: 0.214; TaMin_C: -55; TaMax_C: 125; Cap_Case: 0805; SizeArea_mm2: 2.5; SizeAreaWB_mm2: 6.75; SizeX_mm: 2; SizeY_mm: 1.25; SizeZ_mm: 1.45; AEC Category: Q200; Green_Lifecycle: Active; Green_REACh: Passed
signal-integrity model Cap
simulation model Cap
footprint 0805_HV
footprint 0805_HV1
footprint 0805
footprint 0805M
footprint 0805L
pins: 1, 2

## C0805C102K5RACTU
designator C?  ValueDisplayed: 1000pF  (hidden comment: C0805C102K5RACTU)
CAP, CERM, 1000 pF, 50 V,+/- 10%, X7R, 0805; Manufacturer: Kemet; Polarized: N; CompType: Capacitor; Value: 1000pF; U/M: EA; Cap_F: 0.000000001; Tolerance_%: 10; ESR_ohm: 0.384; Value1: 0.384 ohm; VDC_V: 50; Value2: 50V; IRMS_A: 0.214; TaMin_C: -55; TaMax_C: 125; Cap_Case: 0805; SizeArea_mm2: 2.5; SizeAreaWB_mm2: 6.75; SizeX_mm: 2; SizeY_mm: 1.25; SizeZ_mm: 1.45; AEC Category: Q200; Green_Lifecycle: Active; Green_REACh: Passed
signal-integrity model Cap
simulation model Cap
footprint 0805_HV
footprint 0805_HV1
footprint 0805
footprint 0805M
footprint 0805L
pins: 1, 2

## C0805C102M5RACTU
designator C?  ValueDisplayed: 1000pF  (hidden comment: C0805C102M5RACTU)
CAP, CERM, 1000 pF, 50 V,+/- 20%, X7R, 0805; Manufacturer: Kemet; Polarized: N; CompType: Capacitor; Value: 1000pF; U/M: EA; Cap_F: 0.000000001; Tolerance_%: 20; ESR_ohm: 0.384; Value1: 0.384 ohm; VDC_V: 50; Value2: 50V; IRMS_A: 0.214; TaMin_C: -55; TaMax_C: 125; Cap_Case: 0805; SizeArea_mm2: 2.5; SizeAreaWB_mm2: 6.75; SizeX_mm: 2; SizeY_mm: 1.25; SizeZ_mm: 1.45; AEC Category: Q200; Green_Lifecycle: Active; Green_REACh: Passed
signal-integrity model Cap
simulation model Cap
footprint 0805_HV
footprint 0805_HV1
footprint 0805
footprint 0805M
footprint 0805L
pins: 1, 2

## C0805C103F1GACTU
designator C?  ValueDisplayed: 0.01µF  (hidden comment: C0805C103F1GACTU)
CAP, CERM, 0.01 µF, 100 V,+/- 1%, C0G/NP0, 0805; Manufacturer: Kemet; Polarized: N; CompType: Capacitor; Value: 0.01uF; U/M: EA; Cap_F: 0.00000001; Tolerance_%: 1; VDC_V: 100; Value2: 100V; TaMin_C: -55; TaMax_C: 125; Cap_Case: 0805; SizeArea_mm2: 2.5; SizeAreaWB_mm2: 6.75; SizeX_mm: 2; SizeY_mm: 1.25; SizeZ_mm: 1.45; AEC Category: Q200; Green_Lifecycle: Active; Green_REACh: Passed
signal-integrity model Cap
simulation model Cap
footprint 0805_HV
footprint 0805_HV1
footprint 0805
footprint 0805M
footprint 0805L
pins: 1, 2

## C0805C103K1RACTU
designator C?  ValueDisplayed: 0.01µF  (hidden comment: C0805C103K1RACTU)
CAP, CERM, 0.01 µF, 100 V,+/- 10%, X7R, 0805; Manufacturer: Kemet; Polarized: N; CompType: Capacitor; Value: 0.01uF; U/M: EA; Cap_F: 0.00000001; Tolerance_%: 10; ESR_ohm: 1.739; Value1: 1.739 ohm; VDC_V: 100; Value2: 100V; IRMS_A: 0.411; TaMin_C: -55; TaMax_C: 125; Cap_Case: 0805; SizeArea_mm2: 2.5; SizeAreaWB_mm2: 6.75; SizeX_mm: 2; SizeY_mm: 1.25; SizeZ_mm: 1.45; AEC Category: Q200; Green_Lifecycle: Active; Green_REACh: Passed
signal-integrity model Cap
simulation model Cap
footprint 0805_HV
footprint 0805_HV1
footprint 0805
footprint 0805M
footprint 0805L
pins: 1, 2

## C0805C103K5RACTU
designator C?  ValueDisplayed: 0.01µF  (hidden comment: C0805C103K5RACTU)
CAP, CERM, 0.01 µF, 50 V,+/- 10%, X7R, 0805; Manufacturer: Kemet; Polarized: N; CompType: Capacitor; Value: 0.01uF; U/M: EA; Cap_F: 0.00000001; Tolerance_%: 10; ESR_ohm: 1.739; Value1: 1.739 ohm; VDC_V: 50; Value2: 50V; IRMS_A: 0.411; TaMin_C: -55; TaMax_C: 125; Cap_Case: 0805; SizeArea_mm2: 2.5; SizeAreaWB_mm2: 6.75; SizeX_mm: 2; SizeY_mm: 1.25; SizeZ_mm: 1.45; AEC Category: Q200; Green_Lifecycle: Active; Green_REACh: Passed
signal-integrity model Cap
simulation model Cap
footprint 0805_HV
footprint 0805_HV1
footprint 0805
footprint 0805M
footprint 0805L
pins: 1, 2

## C0805C103KCRACTU
designator C?  ValueDisplayed: 0.01µF  (hidden comment: C0805C103KCRACTU)
CAP, CERM, 0.01 µF, 500 V,+/- 10%, X7R, 0805; Manufacturer: Kemet; Polarized: N; CompType: Capacitor; Value: 0.01uF; U/M: EA; Cap_F: 0.00000001; Tolerance_%: 10; VDC_V: 500; Value2: 500V; TaMin_C: -55; TaMax_C: 125; Cap_Case: 0805; SizeArea_mm2: 2.5; SizeAreaWB_mm2: 6.75; SizeX_mm: 2; SizeY_mm: 1.25; SizeZ_mm: 1.45; AEC Category: Q200; Green_Lifecycle: Not Set; Green_REACh: Incomplete
signal-integrity model Cap
simulation model Cap
footprint 0805_HV
footprint 0805_HV1
footprint 0805
footprint 0805M
footprint 0805L
pins: 1, 2

## C0805C103M5RACTU
designator C?  ValueDisplayed: 0.01µF  (hidden comment: C0805C103M5RACTU)
CAP, CERM, 0.01 µF, 50 V,+/- 20%, X7R, 0805; Manufacturer: Kemet; Polarized: N; CompType: Capacitor; Value: 0.01uF; U/M: EA; Cap_F: 0.00000001; Tolerance_%: 20; ESR_ohm: 1.739; Value1: 1.739 ohm; VDC_V: 50; Value2: 50V; IRMS_A: 0.411; TaMin_C: -55; TaMax_C: 125; Cap_Case: 0805; SizeArea_mm2: 2.5; SizeAreaWB_mm2: 6.75; SizeX_mm: 2; SizeY_mm: 1.25; SizeZ_mm: 1.45; AEC Category: Q200; Green_Lifecycle: Not Set; Green_REACh: Incomplete
signal-integrity model Cap
simulation model Cap
footprint 0805_HV
footprint 0805_HV1
footprint 0805
footprint 0805M
footprint 0805L
pins: 1, 2

## C0805C104J5RACTU
designator C?  ValueDisplayed: 0.1µF  (hidden comment: C0805C104J5RACTU)
CAP, CERM, 0.1 µF, 50 V,+/- 5%, X7R, 0805; Manufacturer: Kemet; Polarized: N; CompType: Capacitor; Value: 0.1uF; U/M: EA; Cap_F: 0.0000001; Tolerance_%: 5; ESR_ohm: 0.064; Value1: 0.064 ohm; VDC_V: 50; Value2: 50V; IRMS_A: 1.64; TaMin_C: -55; TaMax_C: 125; Cap_Case: 0805; SizeArea_mm2: 2.5; SizeAreaWB_mm2: 6.75; SizeX_mm: 2; SizeY_mm: 1.25; SizeZ_mm: 1.45; AEC Category: Q200; Green_Lifecycle: Active; Green_REACh: Passed
signal-integrity model Cap
simulation model Cap
footprint 0805_HV
footprint 0805_HV1
footprint 0805
footprint 0805M
footprint 0805L
pins: 1, 2

## C0805C104K1RACTU
designator C?  ValueDisplayed: 0.1µF  (hidden comment: C0805C104K1RACTU)
CAP, CERM, 0.1 µF, 100 V,+/- 10%, X7R, 0805; Manufacturer: Kemet; Polarized: N; CompType: Capacitor; Value: 0.1uF; U/M: EA; Cap_F: 0.0000001; Tolerance_%: 10; ESR_ohm: 0.064; Value1: 0.064 ohm; VDC_V: 100; Value2: 100V; IRMS_A: 1.64; TaMin_C: -55; TaMax_C: 125; Cap_Case: 0805; SizeArea_mm2: 2.5; SizeAreaWB_mm2: 6.75; SizeX_mm: 2; SizeY_mm: 1.25; SizeZ_mm: 1.45; AEC Category: Q200; Green_Lifecycle: Active; Green_REACh: Passed
signal-integrity model Cap
simulation model Cap
footprint 0805_HV
footprint 0805_HV1
footprint 0805
footprint 0805M
footprint 0805L
pins: 1, 2

## C0805C104K3RACTU
designator C?  ValueDisplayed: 0.1µF  (hidden comment: C0805C104K3RACTU)
CAP, CERM, 0.1 µF, 25 V,+/- 10%, X7R, 0805; Manufacturer: Kemet; Polarized: N; CompType: Capacitor; Value: 0.1uF; U/M: EA; Cap_F: 0.0000001; Tolerance_%: 10; ESR_ohm: 0.064; Value1: 0.064 ohm; VDC_V: 25; Value2: 25V; IRMS_A: 1.64; TaMin_C: -55; TaMax_C: 125; Cap_Case: 0805; SizeArea_mm2: 2.5; SizeAreaWB_mm2: 6.75; SizeX_mm: 2; SizeY_mm: 1.25; SizeZ_mm: 1.45; AEC Category: Q200; Green_Lifecycle: Active; Green_REACh: Passed
signal-integrity model Cap
simulation model Cap
footprint 0805_HV
footprint 0805_HV1
footprint 0805
footprint 0805M
footprint 0805L
pins: 1, 2

## C0805C104K4RACTU
designator C?  ValueDisplayed: 0.1µF  (hidden comment: C0805C104K4RACTU)
CAP, CERM, 0.1 µF, 16 V,+/- 10%, X7R, 0805; Manufacturer: Kemet; Polarized: N; CompType: Capacitor; Value: 0.1uF; U/M: EA; Cap_F: 0.0000001; Tolerance_%: 10; ESR_ohm: 0.064; Value1: 0.064 ohm; VDC_V: 16; Value2: 16V; IRMS_A: 1.64; TaMin_C: -55; TaMax_C: 125; Cap_Case: 0805; SizeArea_mm2: 2.5; SizeAreaWB_mm2: 6.75; SizeX_mm: 2; SizeY_mm: 1.25; SizeZ_mm: 1.45; AEC Category: Q200; Green_Lifecycle: Active; Green_REACh: Passed
signal-integrity model Cap
simulation model Cap
footprint 0805_HV
footprint 0805_HV1
footprint 0805
footprint 0805M
footprint 0805L
pins: 1, 2

## C0805C104K5RACAUTO
designator C?  ValueDisplayed: 0.1µF  (hidden comment: C0805C104K5RACAUTO)
CAP, CERM, 0.1 µF, 50 V,+/- 10%, X7R, AEC-Q200 Grade 0, 0805; Manufacturer: Kemet; Polarized: N; CompType: Capacitor; Value: 0.1uF; U/M: EA; Cap_F: 0.0000001; Tolerance_%: 10; VDC_V: 50; Value2: 50V; TaMin_C: -55; TaMax_C: 125; Cap_Case: 0805; SizeArea_mm2: 2.5; SizeAreaWB_mm2: 6.75; SizeX_mm: 2; SizeY_mm: 1.25; SizeZ_mm: 1.45; AEC Category: Q200; AEC Qualified: Y; AEC Grade: 0; Green_Lifecycle: Not Set; Green_REACh: Incomplete
signal-integrity model Cap
simulation model Cap
footprint 0805_HV
footprint 0805_HV1
footprint 0805
footprint 0805M
footprint 0805L
pins: 1, 2

## C0805C104K5RACTU
designator C?  ValueDisplayed: 0.1µF  (hidden comment: C0805C104K5RACTU)
CAP, CERM, 0.1 µF, 50 V,+/- 10%, X7R, 0805; Manufacturer: Kemet; Polarized: N; CompType: Capacitor; Value: 0.1uF; U/M: EA; Cap_F: 0.0000001; Tolerance_%: 10; ESR_ohm: 0.064; Value1: 0.064 ohm; VDC_V: 50; Value2: 50V; IRMS_A: 1.64; TaMin_C: -55; TaMax_C: 125; Cap_Case: 0805; SizeArea_mm2: 2.5; SizeAreaWB_mm2: 6.75; SizeX_mm: 2; SizeY_mm: 1.25; SizeZ_mm: 1.45; AEC Category: Q200; Green_Lifecycle: Active; Green_REACh: Passed
signal-integrity model Cap
simulation model Cap
footprint 0805_HV
footprint 0805_HV1
footprint 0805
footprint 0805M
footprint 0805L
pins: 1, 2

## C0805C104M5RACTU
designator C?  ValueDisplayed: 0.1µF  (hidden comment: C0805C104M5RACTU)
CAP, CERM, 0.1 µF, 50 V,+/- 20%, X7R, 0805; Manufacturer: Kemet; Polarized: N; CompType: Capacitor; Value: 0.1uF; U/M: EA; Cap_F: 0.0000001; Tolerance_%: 20; ESR_ohm: 0.064; Value1: 0.064 ohm; VDC_V: 50; Value2: 50V; IRMS_A: 1.64; TaMin_C: -55; TaMax_C: 125; Cap_Case: 0805; SizeArea_mm2: 2.5; SizeAreaWB_mm2: 6.75; SizeX_mm: 2; SizeY_mm: 1.25; SizeZ_mm: 1.45; AEC Category: Q200; Green_Lifecycle: Active; Green_REACh: Passed
signal-integrity model Cap
simulation model Cap
footprint 0805_HV
footprint 0805_HV1
footprint 0805
footprint 0805M
footprint 0805L
pins: 1, 2

## C0805C105K3RACTU
designator C?  ValueDisplayed: 1µF  (hidden comment: C0805C105K3RACTU)
CAP, CERM, 1 µF, 25 V,+/- 10%, X7R, 0805; Manufacturer: Kemet; Polarized: N; CompType: Capacitor; Value: 1uF; U/M: EA; Cap_F: 0.000001; Tolerance_%: 10; VDC_V: 25; Value2: 25V; TaMin_C: -55; TaMax_C: 125; Cap_Case: 0805; SizeArea_mm2: 2.5; SizeAreaWB_mm2: 6.75; SizeX_mm: 2; SizeY_mm: 1.25; SizeZ_mm: 1.45; AEC Category: Q200; Green_Lifecycle: Active; Green_REACh: Passed
signal-integrity model Cap
simulation model Cap
footprint 0805_HV
footprint 0805_HV1
footprint 0805
footprint 0805M
footprint 0805L
pins: 1, 2

## C0805C105K4RACTU
designator C?  ValueDisplayed: 1µF  (hidden comment: C0805C105K4RACTU)
CAP, CERM, 1 µF, 16 V,+/- 10%, X7R, 0805; Manufacturer: Kemet; Polarized: N; CompType: Capacitor; Value: 1uF; U/M: EA; Cap_F: 0.000001; Tolerance_%: 10; ESR_ohm: 0.015; Value1: 0.015 ohm; VDC_V: 16; Value2: 16V; IRMS_A: 8.19; TaMin_C: -55; TaMax_C: 125; Cap_Case: 0805; SizeArea_mm2: 2.5; SizeAreaWB_mm2: 6.75; SizeX_mm: 2; SizeY_mm: 1.25; SizeZ_mm: 1.45; AEC Category: Q200; Green_Lifecycle: Active; Green_REACh: Passed
signal-integrity model Cap
simulation model Cap
footprint 0805_HV
footprint 0805_HV1
footprint 0805
footprint 0805M
footprint 0805L
pins: 1, 2

## C0805C105K5RACTU
designator C?  ValueDisplayed: 1µF  (hidden comment: C0805C105K5RACTU)
CAP, CERM, 1 µF, 50 V,+/- 10%, X7R, 0805; Manufacturer: Kemet; Polarized: N; CompType: Capacitor; Value: 1uF; U/M: EA; Cap_F: 0.000001; Tolerance_%: 10; VDC_V: 50; Value2: 50V; TaMin_C: -55; TaMax_C: 125; Cap_Case: 0805; SizeArea_mm2: 2.5; SizeAreaWB_mm2: 6.75; SizeX_mm: 2; SizeY_mm: 1.25; SizeZ_mm: 1.45; AEC Category: Q200; Green_Lifecycle: Not Set; Green_REACh: Incomplete
signal-integrity model Cap
simulation model Cap
footprint 0805_HV
footprint 0805_HV1
footprint 0805
footprint 0805M
footprint 0805L
pins: 1, 2

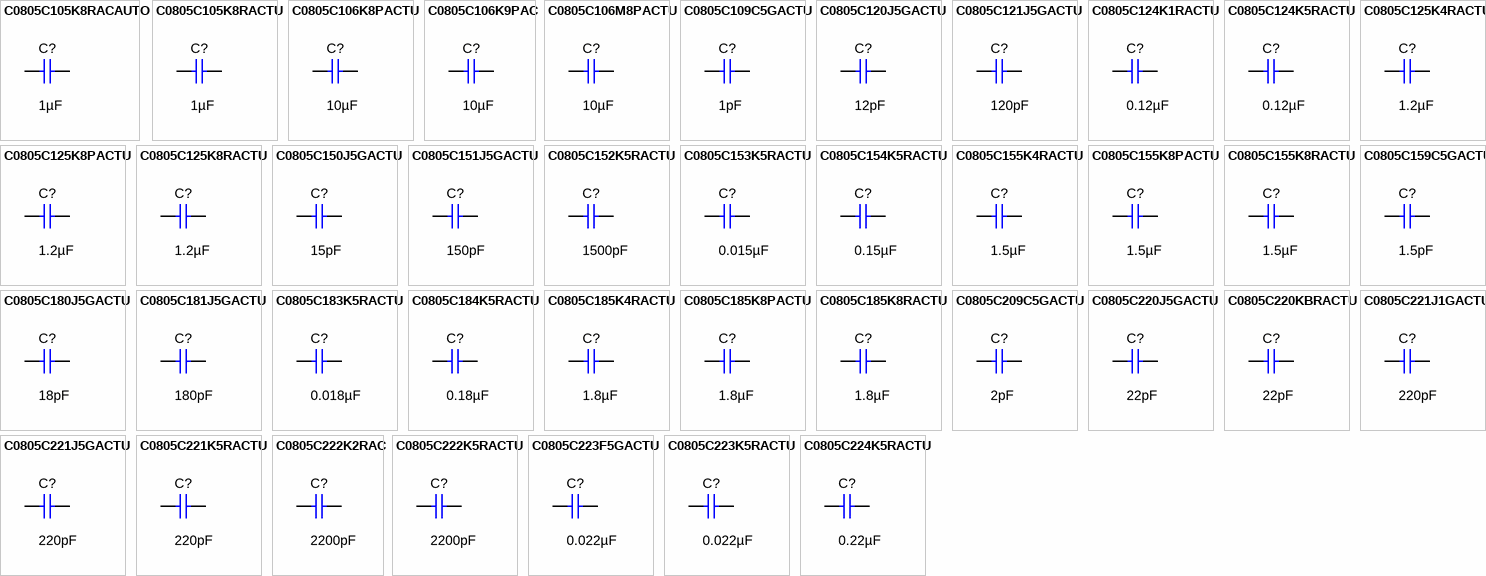
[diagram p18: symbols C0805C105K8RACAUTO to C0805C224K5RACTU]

## C0805C105K8RACAUTO
designator C?  ValueDisplayed: 1µF  (hidden comment: C0805C105K8RACAUTO)
CAP, CERM, 1 µF, 10 V,+/- 10%, X7R, AEC-Q200 Grade 1, 0805; Manufacturer: Kemet; Polarized: N; CompType: Capacitor; Value: 1uF; U/M: EA; Cap_F: 0.000001; Tolerance_%: 10; Value2: 10V; TaMin_C: -55; TaMax_C: 125; Cap_Case: 0805; SizeArea_mm2: 2.5; SizeAreaWB_mm2: 6.75; SizeX_mm: 2; SizeY_mm: 1.25; SizeZ_mm: 1.45; AEC Category: Q200; AEC Qualified: Y; AEC Grade: 1
signal-integrity model Cap
simulation model Cap
footprint 0805_HV
footprint 0805_HV1
footprint 0805
footprint 0805M
footprint 0805L
pins: 1, 2

## C0805C105K8RACTU
designator C?  ValueDisplayed: 1µF  (hidden comment: C0805C105K8RACTU)
CAP, CERM, 1 µF, 10 V,+/- 10%, X7R, 0805; Manufacturer: Kemet; Polarized: N; CompType: Capacitor; Value: 1uF; U/M: EA; Cap_F: 0.000001; Tolerance_%: 10; ESR_ohm: 0.015; Value1: 0.015 ohm; Value2: 10V; IRMS_A: 8.19; TaMin_C: -55; TaMax_C: 125; Cap_Case: 0805; SizeArea_mm2: 2.5; SizeAreaWB_mm2: 6.75; SizeX_mm: 2; SizeY_mm: 1.25; SizeZ_mm: 1.45; AEC Category: Q200; Green_Lifecycle: Not Set; Green_REACh: Incomplete
signal-integrity model Cap
simulation model Cap
footprint 0805_HV
footprint 0805_HV1
footprint 0805
footprint 0805M
footprint 0805L
pins: 1, 2

## C0805C106K8PACTU
designator C?  ValueDisplayed: 10µF  (hidden comment: C0805C106K8PACTU)
CAP, CERM, 10 µF, 10 V,+/- 10%, X5R, 0805; Manufacturer: Kemet; Polarized: N; CompType: Capacitor; Value: 10uF; U/M: EA; Cap_F: 0.00001; Tolerance_%: 10; ESR_ohm: 0.003; Value1: 0.003 ohm; Value2: 10V; IRMS_A: 11.43; TaMin_C: -55; TaMax_C: 85; Cap_Case: 0805; SizeArea_mm2: 2.5; SizeAreaWB_mm2: 6.75; SizeX_mm: 2; SizeY_mm: 1.25; SizeZ_mm: 1.45; AEC Category: Q200; Green_Lifecycle: Active; Green_REACh: Passed
signal-integrity model Cap
simulation model Cap
footprint 0805_HV
footprint 0805_HV1
footprint 0805
footprint 0805M
footprint 0805L
pins: 1, 2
